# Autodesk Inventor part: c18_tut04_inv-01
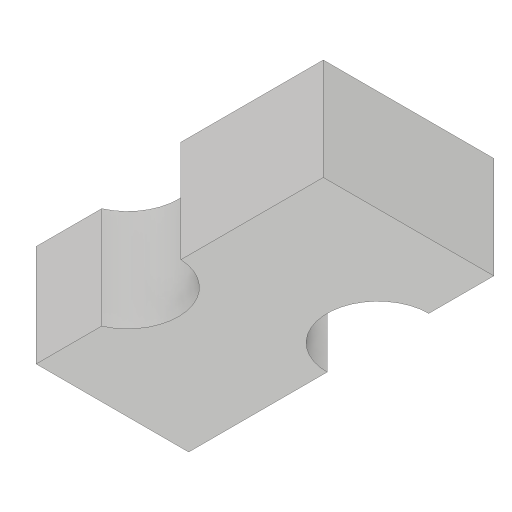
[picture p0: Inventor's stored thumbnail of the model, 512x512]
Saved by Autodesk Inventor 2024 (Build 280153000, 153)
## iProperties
Created: 2017-06
Part Number: c18_tut04_inv-01
Material: Generic
Document SubType Name: Modeling
Designer: CADCIM 00
Density: 1 g/cm^3
Appearance: Default
Author: CADCIM 00
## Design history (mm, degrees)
derived "c18_tut04_inv.ipt"
feature "Solid1::c18_tut04_inv.ipt"
tag "TaggingFeature1"
body "Solid1"
other parameters: "d2" = 16.66667, "d3" = 33.33333, "d4" = 0, "RAD" = 16.66667, "EXT" = 33.33333
